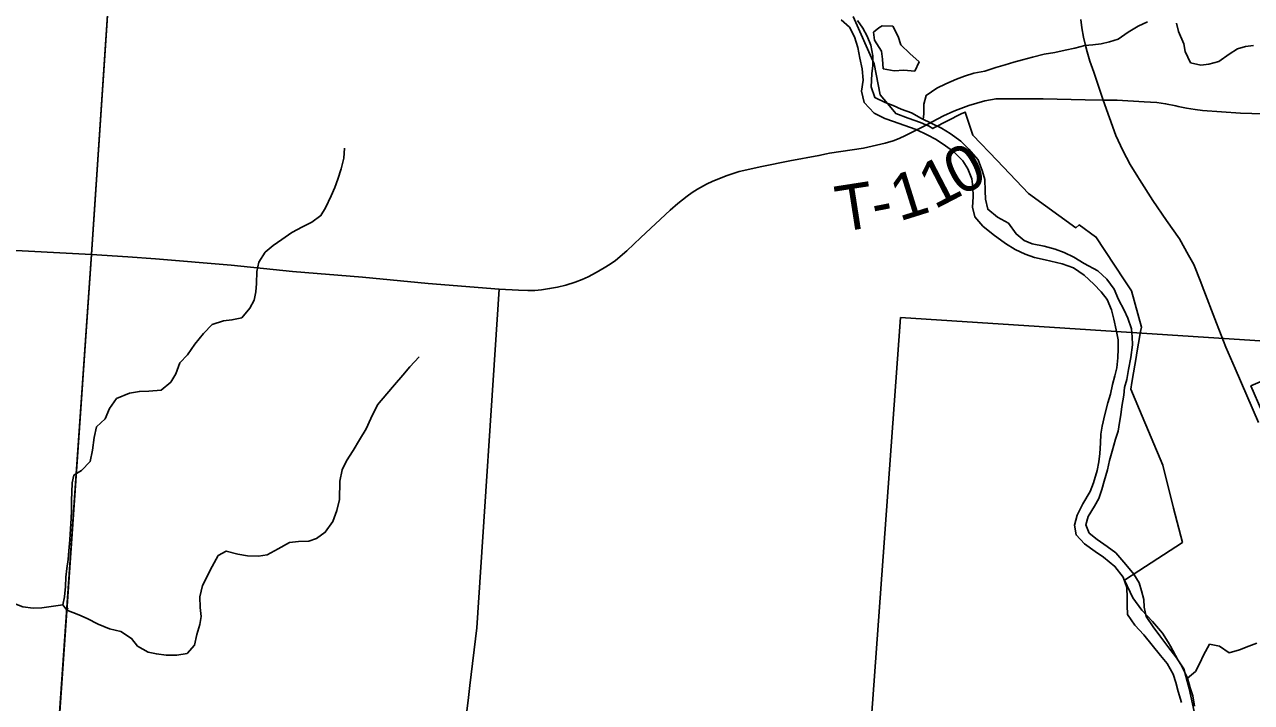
# Model space of a CAD drawing. Extents: x 0 to 34, y 0 to 22.
# Drawn here: x 2.165 to 3.682, y 16.793 to 17.632 of the extents above; entities that cross this region are included whole.
import ezdxf

# ---------------------------------------------------------------- set-up
doc = ezdxf.new("R2010")
doc.units = 0
for name, color, linetype in [('GM_X_City_Street', 7, 'Continuous'), ('GM_X_Corporation', 7, 'Continuous'), ('GM_X_County', 7, 'Continuous'), ('GM_X_Minor_Lake', 7, 'Continuous'), ('GM_X_Minor_River', 7, 'Continuous'), ('GM_X_State_Route', 7, 'Continuous'), ('GM_X_Township_Road', 7, 'Continuous'), ('GM_X_Township_Road_Text', 7, 'Continuous')]:
    doc.layers.add(name, color=color, linetype=linetype)

msp = doc.modelspace()

# ---------------------------------------------------------------- linework, layer by layer
at = {"layer": 'GM_X_City_Street'}
msp.add_line((2.1, 17.3554), (2.2478, 17.3472), dxfattribs=at)
at = {"layer": 'GM_X_Corporation'}
for points in [[(4.3071, 20.9), (2.1, 20.9), (2.1, 14.1), (3.0169, 14.1), (3.0406, 14.4484), (3.1026, 15.287), (3.1745, 16.2606), (2.934, 16.2765), (2.366, 16.3159), (2.2862, 16.3208), (2.1768, 16.323), (2.2478, 17.3472), (2.3155, 18.3567), (3.8153, 18.2543), (3.8503, 18.7566), (3.8611, 18.9124), (3.8924, 19.3621), (3.9019, 19.4987), (3.9133, 19.6628), (3.9816, 20.645), (3.9912, 20.7822), (4.2975, 20.7549)], [(3.2481, 17.2693), (3.7496, 17.2367), (3.6755, 16.2252), (3.1745, 16.2581)]]:
    msp.add_lwpolyline(points, close=True, dxfattribs=at)
for points in [[(2.1, 20.8993), (2.1, 16.3272), (2.1768, 16.3213), (2.1816, 16.3969), (2.2476, 17.3477), (2.2711, 17.6998), (2.2728, 17.718), (2.3153, 18.3572), (3.3358, 18.2876), (3.8151, 18.2549), (3.8501, 18.7572)], [(3.1023, 15.2875), (3.1743, 16.2612), (2.9338, 16.2771), (2.3658, 16.3164), (2.2859, 16.3213), (2.2263, 16.32), (2.2052, 16.32), (2.1768, 16.3213), (2.1816, 16.3969), (2.2476, 17.3477), (2.2711, 17.6998), (2.2728, 17.718), (2.3153, 18.3572), (3.3358, 18.2876), (3.8151, 18.2549), (3.8501, 18.7572)], [(3.8151, 18.2549), (3.3358, 18.2876), (2.3153, 18.3572), (2.2728, 17.718), (2.2711, 17.6998), (2.2476, 17.3477), (2.1816, 16.3969), (2.1768, 16.3213), (2.2052, 16.32), (2.2263, 16.32), (2.2859, 16.3213), (2.3658, 16.3164), (2.9338, 16.2771), (3.1743, 16.2612), (3.1023, 15.2875)], [(3.8151, 18.2549), (3.3358, 18.2876), (2.3153, 18.3572), (2.2728, 17.718), (2.2711, 17.6998), (2.2476, 17.3477), (2.1816, 16.3969), (2.1768, 16.3213), (2.2052, 16.32), (2.2263, 16.32), (2.2859, 16.3213), (2.3658, 16.3164), (2.9338, 16.2771), (3.1743, 16.2612), (3.1023, 15.2875)], [(6.5646, 18.0583), (6.0906, 18.0978), (6.0343, 18.1015), (5.9465, 18.1082), (5.8371, 18.1158), (5.5447, 18.1318), (4.9551, 18.1768), (4.7449, 18.1929), (4.5528, 18.2021), (4.3271, 18.2226), (4.1999, 18.2271), (3.8153, 18.2543), (2.3155, 18.3567), (2.2478, 17.3472), (2.1768, 16.323), (2.2862, 16.3208), (2.366, 16.3159), (2.934, 16.2765), (3.1745, 16.2606), (3.1026, 15.287), (3.0406, 14.4484), (3.0169, 14.1), (8.9, 14.1)], [(3.1895, 17.6418), (3.2155, 17.583), (3.2227, 17.5447), (3.2363, 17.5285), (3.2422, 17.5215), (3.2575, 17.5161), (3.2727, 17.5106), (3.2792, 17.5077), (3.2824, 17.5063), (3.2878, 17.5031), (3.2893, 17.5039), (3.323, 17.5212), (3.328, 17.5235), (3.3376, 17.4949), (3.3676, 17.4634), (3.4061, 17.4229), (3.4648, 17.3805), (3.469, 17.384), (3.4891, 17.3693), (3.4893, 17.3692), (3.4893, 17.3691), (3.5247, 17.316), (3.5337, 17.3025), (3.5459, 17.2576), (3.5449, 17.2522), (3.5399, 17.2232), (3.5398, 17.2225), (3.534, 17.1892), (3.5326, 17.1808), (3.5434, 17.1552), (3.5723, 17.0868), (3.5857, 17.0337), (3.5965, 16.9911), (3.5427, 16.9562), (3.525, 16.9448), (3.5352, 16.9228), (3.5462, 16.9074), (3.5594, 16.8935), (3.5718, 16.8791), (3.5788, 16.8679), (3.5819, 16.863), (3.591, 16.8463), (3.5981, 16.8351), (3.6049, 16.8109), (3.6112, 16.7822)], [(3.6949, 17.1536), (3.6813, 17.1848), (3.705, 17.1951)]]:
    msp.add_lwpolyline(points, dxfattribs=at)
at = {"layer": 'GM_X_County'}
msp.add_lwpolyline([(3.1023, 15.2875), (3.1743, 16.2612), (2.9338, 16.2771), (2.3658, 16.3164), (2.2859, 16.3213), (2.2263, 16.32), (2.2052, 16.32), (2.1768, 16.3213), (2.1816, 16.3969), (2.2476, 17.3477), (2.2711, 17.6998), (2.2728, 17.718), (2.3153, 18.3572), (3.3358, 18.2876), (3.8151, 18.2549)], dxfattribs=at)
at = {"layer": 'GM_X_Minor_Lake'}
for points in [[(3.2383, 17.6297), (3.2253, 17.6301), (3.221, 17.6276), (3.2144, 17.6221)], [(3.2144, 17.6221), (3.2157, 17.6122), (3.2246, 17.5988), (3.2256, 17.5889), (3.2266, 17.5771), (3.2402, 17.5743), (3.2523, 17.5753), (3.2655, 17.5739), (3.271, 17.5856), (3.2594, 17.596), (3.2482, 17.6064), (3.2453, 17.6167), (3.2383, 17.6297)]]:
    msp.add_lwpolyline(points, dxfattribs=at)
at = {"layer": 'GM_X_Minor_River'}
for points in [[(3.1748, 17.6374), (3.1849, 17.6286), (3.1912, 17.6163), (3.1952, 17.6034), (3.1976, 17.5901), (3.2005, 17.5771), (3.2018, 17.563), (3.1997, 17.5494), (3.2029, 17.5353), (3.2156, 17.5219), (3.2287, 17.5156), (3.2393, 17.5117), (3.2521, 17.5073), (3.2675, 17.5018), (3.2811, 17.4955), (3.2919, 17.4897), (3.3036, 17.4819), (3.3133, 17.4746), (3.3252, 17.463), (3.3312, 17.4534), (3.3363, 17.4408), (3.3373, 17.431), (3.3379, 17.4188), (3.3369, 17.4059), (3.3398, 17.3941), (3.3498, 17.3822), (3.3626, 17.3721), (3.3779, 17.3609), (3.3899, 17.3535), (3.4023, 17.3477), (3.4136, 17.3437), (3.4268, 17.3409), (3.4479, 17.336), (3.4619, 17.3309), (3.475, 17.3216), (3.4869, 17.3108), (3.4959, 17.3012), (3.5033, 17.2916), (3.5088, 17.279), (3.5117, 17.2676), (3.5145, 17.2543), (3.517, 17.2417), (3.5172, 17.2307), (3.5167, 17.2197), (3.5154, 17.2072), (3.513, 17.1973), (3.5102, 17.1867), (3.5077, 17.1746), (3.5045, 17.164), (3.5005, 17.1497), (3.4973, 17.1353), (3.4957, 17.1251), (3.4951, 17.1141), (3.4946, 17.1015), (3.4933, 17.0909), (3.4912, 17.0803), (3.4865, 17.0652), (3.4825, 17.0543), (3.4736, 17.0392), (3.4662, 17.0249), (3.463, 17.0128), (3.4651, 17.0006), (3.4756, 16.9895), (3.4887, 16.9802), (3.4988, 16.9732), (3.513, 16.9616), (3.5234, 16.9486), (3.5278, 16.9356), (3.5283, 16.9227), (3.5282, 16.9132), (3.5288, 16.9022), (3.5377, 16.8891), (3.5489, 16.8772), (3.5593, 16.8645), (3.5693, 16.8515), (3.5775, 16.8415), (3.5849, 16.8285), (3.5882, 16.8182), (3.5914, 16.8072), (3.5954, 16.7934)], [(3.4255, 17.3576), (3.4108, 17.3605), (3.4007, 17.3648), (3.3909, 17.3729), (3.3813, 17.3859), (3.3678, 17.3937), (3.3558, 17.4034), (3.353, 17.4159), (3.3527, 17.4262), (3.3522, 17.4399), (3.3493, 17.4501), (3.3438, 17.4646), (3.3326, 17.4777), (3.3226, 17.4873), (3.3095, 17.497), (3.2986, 17.5036), (3.2866, 17.5095), (3.2738, 17.5157), (3.2614, 17.5224), (3.2486, 17.5271), (3.2388, 17.5314), (3.229, 17.5353), (3.2162, 17.5416), (3.2119, 17.5546), (3.2125, 17.5709), (3.2138, 17.5811), (3.2136, 17.5929), (3.2115, 17.6062), (3.2067, 17.6173), (3.2016, 17.6272), (3.1949, 17.6368)], [(3.1949, 17.6368), (3.2016, 17.6272), (3.2067, 17.6173), (3.2115, 17.6062), (3.2136, 17.5929), (3.2138, 17.5811), (3.2125, 17.5709), (3.2119, 17.5546), (3.2162, 17.5416), (3.229, 17.5353), (3.2388, 17.5314), (3.2486, 17.5271), (3.2614, 17.5224), (3.2738, 17.5157), (3.2866, 17.5095), (3.2986, 17.5036), (3.3095, 17.497), (3.3226, 17.4873), (3.3326, 17.4777), (3.3438, 17.4646), (3.3493, 17.4501), (3.3522, 17.4399), (3.3527, 17.4262), (3.353, 17.4159), (3.3558, 17.4034), (3.3678, 17.3937), (3.3813, 17.3859), (3.3909, 17.3729), (3.4007, 17.3648), (3.4108, 17.3605), (3.4255, 17.3576)], [(3.2759, 17.5147), (3.2769, 17.521), (3.277, 17.5331), (3.2799, 17.5441), (3.2928, 17.553), (3.3039, 17.5582), (3.3172, 17.5641), (3.3271, 17.5678), (3.3385, 17.5714), (3.3522, 17.5742), (3.3659, 17.5786), (3.3773, 17.5819), (3.3883, 17.5851), (3.3989, 17.588), (3.4111, 17.5913), (3.4255, 17.5949), (3.4388, 17.5973), (3.4517, 17.6002), (3.4635, 17.6023), (3.476, 17.6056), (3.4859, 17.6066), (3.4961, 17.6079), (3.5063, 17.6101), (3.517, 17.6137), (3.5296, 17.6223), (3.5418, 17.6297), (3.5532, 17.6349)], [(3.5892, 17.6332), (3.5917, 17.6229), (3.5983, 17.608), (3.6, 17.5985), (3.6066, 17.5844), (3.6191, 17.5816), (3.6293, 17.5826), (3.6415, 17.5858), (3.6545, 17.5951), (3.6648, 17.6018), (3.6747, 17.6047), (3.6845, 17.6057)], [(2.2172, 16.9074), (2.2124, 16.9143), (2.2144, 16.9242), (2.2157, 16.9367), (2.2159, 16.9485), (2.2175, 16.9591), (2.2188, 16.9704), (2.2198, 16.981), (2.2211, 16.9947), (2.2217, 17.008), (2.2226, 17.0209), (2.2231, 17.0304), (2.2229, 17.0436), (2.2234, 17.0531), (2.224, 17.0649), (2.226, 17.0747), (2.2355, 17.0803), (2.2463, 17.0915), (2.2492, 17.1055), (2.2513, 17.1211), (2.2541, 17.1343), (2.2648, 17.144), (2.2699, 17.1569), (2.2788, 17.1693), (2.2948, 17.1759), (2.307, 17.178), (2.3187, 17.1782), (2.3338, 17.1795), (2.3457, 17.1896), (2.3519, 17.1998), (2.357, 17.2134), (2.3663, 17.2235), (2.3755, 17.2363), (2.3863, 17.2498), (2.3971, 17.2606), (2.4111, 17.2654), (2.4214, 17.2664), (2.4335, 17.2692), (2.4435, 17.2809), (2.449, 17.2907), (2.451, 17.3013), (2.4519, 17.3115), (2.4521, 17.3263), (2.4546, 17.338), (2.4627, 17.3501), (2.4723, 17.3583), (2.4833, 17.3657), (2.4956, 17.3747), (2.5085, 17.3817), (2.5204, 17.3872), (2.5314, 17.3954), (2.5369, 17.4052), (2.5443, 17.4199), (2.5486, 17.4301), (2.5525, 17.4403), (2.5565, 17.4532), (2.5597, 17.4664), (2.5606, 17.4789)], [(3.6116, 16.789), (3.6095, 16.8016), (3.6062, 16.8115), (3.6026, 16.8237), (3.596, 16.8382), (3.5897, 16.8482), (3.5786, 16.8628), (3.5685, 16.8758), (3.5604, 16.8869), (3.5519, 16.8996), (3.5494, 16.9114), (3.5488, 16.9209), (3.5459, 16.9315), (3.543, 16.9414), (3.5363, 16.9522), (3.5267, 16.9641), (3.5144, 16.9783), (3.5035, 16.9864), (3.4911, 16.9949), (3.4814, 17.003), (3.477, 17.0133), (3.4802, 17.0235), (3.488, 17.036), (3.493, 17.0458), (3.4969, 17.0567), (3.4997, 17.0669), (3.5037, 17.0813), (3.5065, 17.0927), (3.5097, 17.104), (3.5137, 17.1191), (3.5169, 17.1289), (3.5189, 17.1395), (3.5202, 17.149), (3.5215, 17.1593), (3.524, 17.1733), (3.5249, 17.1831), (3.5277, 17.193), (3.5297, 17.2051), (3.5326, 17.2198), (3.5347, 17.2358), (3.5345, 17.2456), (3.5335, 17.2555), (3.5291, 17.2685), (3.5247, 17.2784), (3.5177, 17.2918), (3.5122, 17.3044), (3.5029, 17.3167), (3.4921, 17.3271), (3.4752, 17.3364), (3.4624, 17.3442), (3.4504, 17.3497), (3.4391, 17.354), (3.4255, 17.3576)], [(2.2185, 16.9106), (2.2172, 16.9074), (2.2323, 16.9019), (2.2424, 16.8972), (2.2559, 16.8902), (2.2702, 16.8847), (2.2842, 16.8811), (2.2973, 16.8726), (2.3047, 16.863), (2.3179, 16.8556), (2.3281, 16.8535), (2.3402, 16.8518), (2.3534, 16.852), (2.3659, 16.8541), (2.3751, 16.8643), (2.378, 16.8775), (2.3816, 16.89), (2.3832, 16.8998), (2.3822, 16.9109), (2.3817, 16.9241), (2.3849, 16.9381), (2.397, 16.9615), (2.4044, 16.9751), (2.4143, 16.9806), (2.4286, 16.977), (2.4407, 16.9746), (2.4543, 16.9744), (2.4649, 16.9761), (2.4787, 16.9835), (2.4924, 16.9913), (2.5038, 16.9923), (2.5166, 16.9929), (2.5261, 16.9962), (2.5368, 17.004), (2.5461, 17.0171), (2.5512, 17.0307), (2.5544, 17.0444), (2.5548, 17.0671), (2.5576, 17.0811), (2.5631, 17.0924), (2.5712, 17.1052), (2.579, 17.118), (2.5875, 17.132), (2.593, 17.1444), (2.6012, 17.1614), (2.6131, 17.1749), (2.6223, 17.1861), (2.6327, 17.1981), (2.6412, 17.2083), (2.6527, 17.221)], [(2.1, 16.9415), (2.1053, 16.9416), (2.1197, 16.9419), (2.1303, 16.9392), (2.1393, 16.9297), (2.1487, 16.9171), (2.163, 16.9117), (2.1758, 16.9101), (2.1864, 16.9104), (2.2124, 16.9143)], [(3.6026, 16.8237), (3.6126, 16.8319), (3.618, 16.8421), (3.6227, 16.8519), (3.6301, 16.8655), (3.6422, 16.863), (3.6545, 16.8549), (3.6671, 16.8585), (3.6785, 16.8629), (3.6884, 16.8669)]]:
    msp.add_lwpolyline(points, dxfattribs=at)
at = {"layer": 'GM_X_State_Route'}
for points in [[(3.471, 17.6381), (3.4722, 17.6277), (3.4743, 17.616), (3.4762, 17.6075), (3.4786, 17.5979), (3.4822, 17.5862), (3.4869, 17.5726), (3.4984, 17.5383)], [(3.4984, 17.5383), (3.516, 17.5383), (3.5493, 17.5363), (3.5648, 17.5352), (3.5758, 17.5337), (3.5884, 17.5312), (3.5914, 17.5305)], [(3.4984, 17.5383), (3.5143, 17.4944), (3.5227, 17.4758), (3.532, 17.4585), (3.5415, 17.4435), (3.5436, 17.4401)], [(3.5914, 17.5305), (3.6016, 17.5283), (3.6122, 17.5266), (3.6214, 17.5254), (3.6685, 17.522), (3.7238, 17.5204), (3.7259, 17.5204)], [(3.5436, 17.4401), (3.5601, 17.4143), (3.5767, 17.3892), (3.5928, 17.3666), (3.604, 17.3467), (3.6105, 17.3351), (3.6193, 17.3131)], [(3.6193, 17.3131), (3.6211, 17.3085), (3.6386, 17.2625), (3.6504, 17.2327), (3.6616, 17.2065), (3.6906, 17.1398)]]:
    msp.add_lwpolyline(points, dxfattribs=at)
at = {"layer": 'GM_X_Township_Road'}
for points in [[(3.3138, 17.5244), (3.3193, 17.5267), (3.3324, 17.5315), (3.3524, 17.5374), (3.3661, 17.54), (3.3876, 17.54), (3.4245, 17.5398), (3.4761, 17.5386), (3.4984, 17.5383)], [(3.2871, 17.5115), (3.3011, 17.519), (3.3138, 17.5244)], [(3.1566, 17.4717), (3.1604, 17.4725), (3.2021, 17.479), (3.229, 17.4852), (3.2388, 17.488), (3.2462, 17.4908), (3.2541, 17.4944), (3.2757, 17.5053), (3.2871, 17.5115)], [(2.2478, 17.3472), (2.2929, 17.3444), (2.327, 17.3419), (2.4204, 17.334), (2.4962, 17.3265), (2.5829, 17.3192), (2.664, 17.3115), (2.7519, 17.3046), (2.7757, 17.3031), (2.7874, 17.3029), (2.7959, 17.303), (2.8041, 17.3037), (2.8142, 17.3052), (2.8238, 17.307), (2.8341, 17.3096), (2.8457, 17.3132), (2.8543, 17.3165), (2.8617, 17.3198), (2.8718, 17.325), (2.8818, 17.3307), (2.8892, 17.3354), (2.8958, 17.3401), (2.9098, 17.352), (2.9271, 17.3682), (2.9632, 17.4021), (2.9727, 17.4104), (2.9842, 17.4195), (2.9904, 17.4239), (2.997, 17.428), (3.008, 17.4342), (3.0158, 17.4379), (3.0232, 17.4411), (3.0326, 17.4446), (3.0487, 17.4501), (3.0766, 17.4562), (3.1112, 17.463), (3.1472, 17.4697), (3.1566, 17.4717)], [(2.709, 16.7591), (2.7138, 16.7998), (2.7155, 16.8145), (2.7241, 16.8859), (2.7519, 17.3046)]]:
    msp.add_lwpolyline(points, dxfattribs=at)

# ---------------------------------------------------------------- texts
at = {"layer": 'GM_X_Township_Road_Text'}
for s, rotation, p in [('0', 27.4851, (3.321, 17.4187)), ('1', 27.4364, (3.2899, 17.4026)), ('1', 17.4149, (3.2465, 17.388)), ('T', 8.8247, (3.1725, 17.3749)), ('-', 11.0156, (3.2169, 17.3818))]:
    msp.add_text(s, height=0.0568, rotation=rotation, dxfattribs=at).set_placement(p)

doc.saveas('drawing.dxf')
